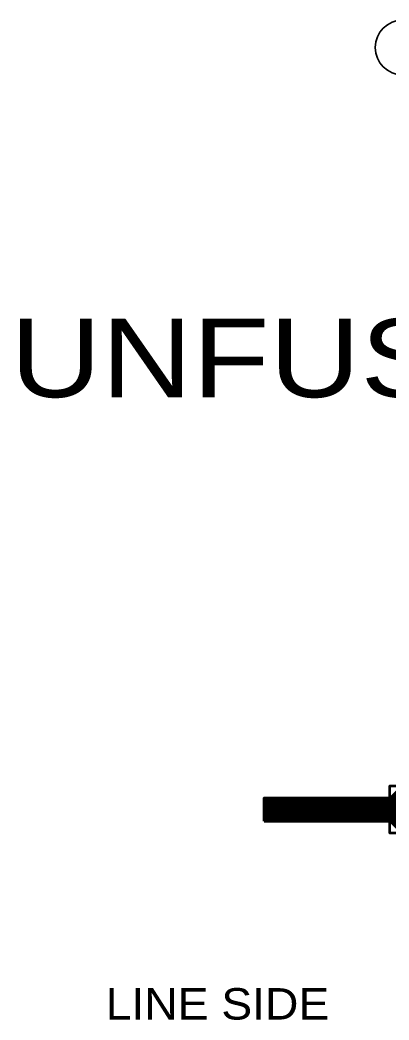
# Model space of a CAD drawing. Extents: x -1 to 679, y 0 to 440.
# Drawn here: x 450.6 to 474.1, y 227.7 to 291.3 of the extents above; entities that cross this region are included whole.
import ezdxf
from ezdxf.enums import TextEntityAlignment as Align

# ---------------------------------------------------------------- set-up
doc = ezdxf.new("R2010")
doc.units = 0
doc.header["$LTSCALE"] = 0.8
doc.layers.add('1', color=7, linetype='Continuous', lineweight=53)

msp = doc.modelspace()

# ---------------------------------------------------------------- linework, layer by layer
at = {"layer": '1'}
for p, q in [((474.9673, 242.5712), (472.7173, 240.3212)), ((472.8587, 240.3212), (475.1087, 242.5712)), ((473.0002, 240.3212), (475.2502, 242.5712)), ((473.1416, 240.3212), (475.3916, 242.5712)), ((473.2831, 240.3212), (475.5331, 242.5712)), ((473.4245, 240.3212), (475.6745, 242.5712)), ((466.1543, 241.8192), (466.1563, 241.8212)), ((466.1543, 241.6778), (466.2978, 241.8212)), ((466.1543, 241.5364), (466.4392, 241.8212)), ((466.1543, 241.395), (466.5806, 241.8212)), ((466.1543, 241.2536), (466.722, 241.8212)), ((466.1543, 241.1122), (466.8634, 241.8212)), ((466.1543, 240.9707), (467.0048, 241.8212)), ((466.1543, 240.8293), (467.1463, 241.8212)), ((466.1543, 240.6878), (467.2877, 241.8212)), ((466.1543, 240.5464), (467.4292, 241.8212)), ((466.1543, 240.405), (467.5706, 241.8212)), ((466.1543, 241.8212), (466.1543, 240.3212)), ((466.1543, 241.8212), (474.1543, 241.8212)), ((467.5571, 240.3212), (466.1543, 241.724)), ((467.4157, 240.3212), (466.1543, 241.5826)), ((467.2742, 240.3212), (466.1543, 241.4412)), ((467.1328, 240.3212), (466.1543, 241.2997)), ((467.6985, 240.3212), (466.1985, 241.8212)), ((466.212, 240.3212), (467.712, 241.8212)), ((467.8399, 240.3212), (466.3399, 241.8212)), ((466.3534, 240.3212), (467.8534, 241.8212)), ((467.9813, 240.3212), (466.4813, 241.8212)), ((466.4948, 240.3212), (467.9948, 241.8212)), ((468.1227, 240.3212), (466.6227, 241.8212)), ((466.6362, 240.3212), (468.1362, 241.8212)), ((468.2642, 240.3212), (466.7642, 241.8212)), ((466.7777, 240.3212), (468.2777, 241.8212)), ((468.4056, 240.3212), (466.9056, 241.8212)), ((466.9191, 240.3212), (468.4191, 241.8212)), ((468.547, 240.3212), (467.047, 241.8212)), ((467.0605, 240.3212), (468.5605, 241.8212)), ((468.6884, 240.3212), (467.1884, 241.8212)), ((467.2019, 240.3212), (468.7019, 241.8212)), ((468.8298, 240.3212), (467.3298, 241.8212)), ((467.3433, 240.3212), (468.8433, 241.8212)), ((468.9712, 240.3212), (467.4712, 241.8212)), ((467.4847, 240.3212), (468.9847, 241.8212)), ((469.1127, 240.3212), (467.6127, 241.8212)), ((467.6262, 240.3212), (469.1262, 241.8212)), ((469.2542, 240.3212), (467.7542, 241.8212)), ((467.7676, 240.3212), (469.2676, 241.8212)), ((469.3956, 240.3212), (467.8956, 241.8212)), ((467.909, 240.3212), (469.409, 241.8212)), ((469.537, 240.3212), (468.037, 241.8212)), ((468.0504, 240.3212), (469.5504, 241.8212)), ((469.6784, 240.3212), (468.1784, 241.8212)), ((468.1919, 240.3212), (469.6919, 241.8212)), ((469.8198, 240.3212), (468.3198, 241.8212)), ((469.8333, 241.8212), (468.3333, 240.3212)), ((469.9613, 240.3212), (468.4613, 241.8212)), ((468.4747, 240.3212), (469.9747, 241.8212)), ((470.1027, 240.3212), (468.6027, 241.8212)), ((468.6162, 240.3212), (470.1162, 241.8212)), ((470.2441, 240.3212), (468.7441, 241.8212)), ((468.7576, 240.3212), (470.2576, 241.8212)), ((470.3855, 240.3212), (468.8855, 241.8212)), ((468.899, 240.3212), (470.399, 241.8212)), ((470.5269, 240.3212), (469.0269, 241.8212)), ((469.0404, 240.3212), (470.5404, 241.8212)), ((470.6683, 240.3212), (469.1683, 241.8212)), ((469.1818, 240.3212), (470.6818, 241.8212)), ((470.8098, 240.3212), (469.3098, 241.8212)), ((469.3232, 240.3212), (470.8232, 241.8212)), ((470.9512, 240.3212), (469.4512, 241.8212)), ((470.9647, 241.8212), (469.4647, 240.3212)), ((471.0926, 240.3212), (469.5926, 241.8212)), ((469.6061, 240.3212), (471.1061, 241.8212)), ((471.234, 240.3212), (469.734, 241.8212)), ((469.7475, 240.3212), (471.2475, 241.8212)), ((471.3754, 240.3212), (469.8754, 241.8212)), ((469.8889, 240.3212), (471.3889, 241.8212)), ((471.5168, 240.3212), (470.0168, 241.8212)), ((470.0303, 240.3212), (471.5303, 241.8212)), ((471.6583, 240.3212), (470.1583, 241.8212)), ((470.1717, 240.3212), (471.6717, 241.8212)), ((471.7997, 240.3212), (470.2997, 241.8212)), ((470.3132, 240.3212), (471.8132, 241.8212)), ((471.9412, 240.3212), (470.4412, 241.8212)), ((470.4546, 240.3212), (471.9546, 241.8212)), ((472.0826, 240.3212), (470.5826, 241.8212)), ((470.596, 240.3212), (472.096, 241.8212)), ((472.224, 240.3212), (470.724, 241.8212)), ((470.7375, 240.3212), (472.2375, 241.8212)), ((472.3654, 240.3212), (470.8654, 241.8212)), ((470.8789, 240.3212), (472.3789, 241.8212)), ((472.5068, 240.3212), (471.0068, 241.8212)), ((471.0203, 240.3212), (472.5203, 241.8212)), ((472.6482, 240.3212), (471.1482, 241.8212)), ((471.1617, 240.3212), (472.6617, 241.8212)), ((472.7897, 240.3212), (471.2897, 241.8212)), ((471.3032, 240.3212), (472.8032, 241.8212)), ((472.9311, 240.3212), (471.4311, 241.8212)), ((471.4446, 240.3212), (472.9446, 241.8212)), ((473.0725, 240.3212), (471.5725, 241.8212)), ((471.586, 240.3212), (473.086, 241.8212)), ((473.2139, 240.3212), (471.7139, 241.8212)), ((471.7274, 240.3212), (473.2274, 241.8212)), ((473.3553, 240.3212), (471.8553, 241.8212)), ((471.8688, 240.3212), (473.3688, 241.8212)), ((473.4967, 240.3212), (471.9967, 241.8212)), ((472.0102, 240.3212), (473.5102, 241.8212)), ((473.6382, 240.3212), (472.1382, 241.8212)), ((472.1517, 240.3212), (473.6517, 241.8212)), ((473.7796, 240.3212), (472.2796, 241.8212)), ((472.2931, 240.3212), (473.7931, 241.8212)), ((473.921, 240.3212), (472.421, 241.8212)), ((472.4345, 240.3212), (473.9345, 241.8212)), ((474.0624, 240.3212), (472.5624, 241.8212)), ((472.5759, 240.3212), (474.0759, 241.8212)), ((474.9538, 239.5712), (472.7038, 241.8212)), ((475.0953, 239.5712), (472.8453, 241.8212)), ((475.2367, 239.5712), (472.9867, 241.8212)), ((475.3782, 239.5712), (473.1282, 241.8212)), ((475.5196, 239.5712), (473.2696, 241.8212)), ((475.661, 239.5712), (473.411, 241.8212)), ((474.6543, 240.7193), (473.5524, 241.8212)), ((473.5659, 240.3212), (474.6543, 241.4097)), ((474.6543, 240.8607), (473.6938, 241.8212)), ((474.6543, 241.0022), (473.8352, 241.8212)), ((474.6543, 241.1436), (473.9767, 241.8212)), ((466.9914, 240.3212), (466.1543, 241.1583)), ((466.85, 240.3212), (466.1543, 241.0169)), ((466.7086, 240.3212), (466.1543, 240.8755)), ((466.5671, 240.3212), (466.1543, 240.734)), ((473.7073, 240.3212), (474.6543, 241.2682)), ((473.8487, 240.3212), (474.6543, 241.1268)), ((473.9902, 240.3212), (474.6543, 240.9854)), ((466.4257, 240.3212), (466.1543, 240.5926)), ((466.2842, 240.3212), (466.1543, 240.4512)), ((466.1543, 240.3212), (474.1543, 240.3212))]:
    msp.add_line(p, q, dxfattribs=at)
msp.add_lwpolyline([(466.1543, 240.3212), (466.1543, 241.8212), (474.1543, 241.8212), (474.1543, 242.5712), (484.1543, 242.5712), (491.1543, 242.5712), (491.6543, 244.0712), (503.4783, 244.0712), (501.4783, 241.9462), (501.4783, 240.1962), (503.4783, 238.0712), (491.6543, 238.0712), (491.1543, 239.5712), (484.1543, 239.5712), (474.1543, 239.5712), (474.1543, 240.3212)], close=True, dxfattribs=at)
at = {"layer": '1', "lineweight": 35}
msp.add_circle((474.9803, 289.5818), 1.75, dxfattribs=at)

# ---------------------------------------------------------------- texts
at = {"layer": '1', "width": 1.2}
msp.add_text('UNFUSED "Y" CONNECTOR KIT FOR POLE BASE', height=5, dxfattribs=at).set_placement((543.5786, 267.319), align=Align.CENTER)
at = {"layer": '1', "width": 1.1}
msp.add_text('LINE SIDE', height=2, dxfattribs=at).set_placement((456.0812, 227.6958))

doc.saveas('drawing.dxf')
